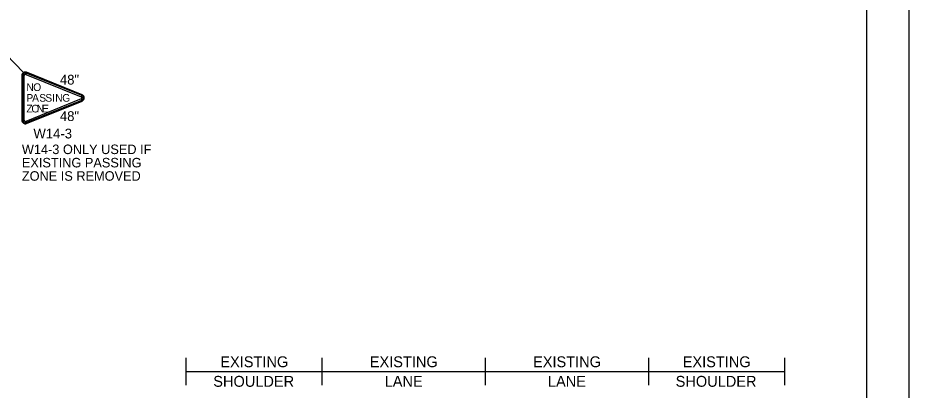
# Model space of a CAD drawing. Extents: x 99976 to 100136, y 99905 to 100011.
# Drawn here: x 100029.51 to 100036.06, y 99943.29 to 99946.03 of the extents above; entities that cross this region are included whole.
import ezdxf

# ---------------------------------------------------------------- set-up
doc = ezdxf.new("R2010")
doc.units = 0
for name, color, linetype in [('Default', 7, 'Continuous'), ('SH_GI_PlotLimits', 7, 'Continuous'), ('SH_GI_SheetBorder', 7, 'Continuous'), ('TR_SN_ConstructionSigns', 7, 'Continuous'), ('TR_WZ_WorkZoneDetails', 7, 'Continuous'), ('TR_WZ_WorkZoneTextCurrent', 7, 'Continuous')]:
    doc.layers.add(name, color=color, linetype=linetype)

msp = doc.modelspace()

# ---------------------------------------------------------------- linework, layer by layer
at = {"layer": 'Default'}
for p, q in [((100029.548, 99945.6015), (100029.5579, 99945.6015)), ((100029.5579, 99945.6015), (100029.548, 99945.6015)), ((100029.548, 99945.6015), (100029.548, 99945.6015)), ((100029.548, 99945.6015), (100029.5579, 99945.6015)), ((100029.5695, 99945.6094), (100029.5732, 99945.6185)), ((100029.5732, 99945.6185), (100029.5695, 99945.6094)), ((100029.5695, 99945.6094), (100029.5732, 99945.6185))]:
    msp.add_line(p, q, dxfattribs=at)
for radius in [0.0183, 0.0183, 0.00844, 0.00844]:
    msp.add_arc((100029.5663, 99945.6015), radius, 67.97569, 180.00001, dxfattribs=at)
at = {"layer": 'SH_GI_PlotLimits'}
msp.add_lwpolyline([(100019.0625, 99939.6875), (100036.0625, 99939.6875), (100036.0625, 99950.6875), (100019.0625, 99950.6875)], close=True, dxfattribs=at)
at = {"layer": 'SH_GI_SheetBorder'}
msp.add_line((100035.75, 99950.375), (100035.75, 99940), dxfattribs=at)
at = {"layer": 'TR_SN_ConstructionSigns'}
for p, q in [((100029.541, 99945.6015), (100029.541, 99945.2716)), ((100029.548, 99945.6015), (100029.548, 99945.2716)), ((100029.548, 99945.6015), (100029.548, 99945.2716)), ((100029.5579, 99945.6015), (100029.548, 99945.6015)), ((100029.5579, 99945.2716), (100029.5579, 99945.6015)), ((100029.5579, 99945.2716), (100029.5579, 99945.6015)), ((100029.5732, 99945.6185), (100029.5695, 99945.6094)), ((100029.5695, 99945.6094), (100029.9773, 99945.4444)), ((100029.5695, 99945.6094), (100029.9773, 99945.4444)), ((100029.981, 99945.4535), (100029.5732, 99945.6185)), ((100029.981, 99945.4535), (100029.5732, 99945.6185)), ((100029.9836, 99945.46), (100029.5758, 99945.625)), ((100029.9773, 99945.4288), (100029.5695, 99945.2638)), ((100029.9773, 99945.4288), (100029.5695, 99945.2638)), ((100029.5732, 99945.2547), (100029.981, 99945.4196)), ((100029.5732, 99945.2547), (100029.981, 99945.4196)), ((100029.5758, 99945.2482), (100029.9836, 99945.4131)), ((100029.981, 99945.4535), (100029.9773, 99945.4444)), ((100029.9773, 99945.4444), (100029.981, 99945.4535)), ((100029.981, 99945.4535), (100029.9773, 99945.4444)), ((100029.9773, 99945.4444), (100029.981, 99945.4535)), ((100029.9773, 99945.4288), (100029.981, 99945.4196)), ((100029.981, 99945.4196), (100029.9773, 99945.4288)), ((100029.9773, 99945.4288), (100029.981, 99945.4196)), ((100029.981, 99945.4196), (100029.9773, 99945.4288)), ((100029.981, 99945.4535), (100029.981, 99945.4535)), ((100029.5579, 99945.2716), (100029.548, 99945.2716)), ((100029.548, 99945.2716), (100029.5579, 99945.2716)), ((100029.5579, 99945.2716), (100029.548, 99945.2716)), ((100029.548, 99945.2716), (100029.5579, 99945.2716)), ((100029.5732, 99945.2547), (100029.5695, 99945.2638)), ((100029.5695, 99945.2638), (100029.5732, 99945.2547)), ((100029.5732, 99945.2547), (100029.5695, 99945.2638)), ((100029.5695, 99945.2638), (100029.5732, 99945.2547)), ((100029.5732, 99945.2547), (100029.5732, 99945.2547))]:
    msp.add_line(p, q, dxfattribs=at)
for centre, radius, start, end in [((100029.5663, 99945.6015), 0.0253, 67.97569, 180), ((100029.9741, 99945.4366), 0.00844, 292.02433, 67.97569), ((100029.9741, 99945.4366), 0.00844, 292.02433, 67.97569), ((100029.9741, 99945.4366), 0.0183, 292.02433, 67.97569), ((100029.9741, 99945.4366), 0.0183, 292.02433, 67.97569), ((100029.9741, 99945.4366), 0.0253, 292.02432, 67.9757), ((100029.5663, 99945.2716), 0.0253, 180, 292.02432), ((100029.5663, 99945.2716), 0.0183, 180.00001, 292.02433), ((100029.5663, 99945.2716), 0.0183, 180.00001, 292.02433), ((100029.5663, 99945.2716), 0.00844, 180.00001, 292.02433), ((100029.5663, 99945.2716), 0.00844, 180.00001, 292.02433)]:
    msp.add_arc(centre, radius, start, end, dxfattribs=at)
at = {"layer": 'TR_WZ_WorkZoneDetails'}
for p, q in [((100029.5522, 99945.6225), (100029.3425, 99945.8393)), ((100030.7479, 99943.3244), (100030.7479, 99943.5244)), ((100031.7479, 99943.3244), (100031.7479, 99943.5244)), ((100032.9479, 99943.3244), (100032.9479, 99943.5244)), ((100034.1479, 99943.3244), (100034.1479, 99943.5244)), ((100035.1479, 99943.3244), (100035.1479, 99943.5244)), ((100030.7479, 99943.4244), (100031.7479, 99943.4244)), ((100031.7479, 99943.4244), (100032.9479, 99943.4244)), ((100032.9479, 99943.4244), (100034.1479, 99943.4244)), ((100034.1479, 99943.4244), (100035.1479, 99943.4244))]:
    msp.add_line(p, q, dxfattribs=at)

# ---------------------------------------------------------------- texts
at = {"layer": 'TR_SN_ConstructionSigns'}
for s, height, p in [('48"', 0.072, (100029.8204, 99945.5347)), ('N', 0.0562, (100029.5744, 99945.4872)), ('O', 0.0562, (100029.6244, 99945.4872)), ('P', 0.0562, (100029.5744, 99945.4085)), ('A', 0.0562, (100029.6163, 99945.4085)), ('S', 0.0562, (100029.6691, 99945.4085)), ('S', 0.0562, (100029.7135, 99945.4085)), ('I', 0.0562, (100029.7622, 99945.4085)), ('N', 0.0562, (100029.786, 99945.4085)), ('G', 0.0562, (100029.8378, 99945.4085)), ('Z', 0.0562, (100029.5744, 99945.3297)), ('O', 0.0562, (100029.6108, 99945.3297)), ('N', 0.0562, (100029.6505, 99945.3297)), ('E', 0.0562, (100029.6891, 99945.3297))]:
    msp.add_text(s, height=height, dxfattribs=at).set_placement(p)
for s, p in [('48"', (100029.8204, 99945.2665)), ('W14-3', (100029.6261, 99945.1383))]:
    msp.add_text(s, height=0.072, rotation=360, dxfattribs=at).set_placement(p)
at = {"layer": 'TR_WZ_WorkZoneDetails'}
for s, p in [('EXISTING', (100030.9996, 99943.4564)), ('EXISTING', (100032.0981, 99943.4564)), ('EXISTING', (100033.2981, 99943.4564)), ('EXISTING', (100034.3981, 99943.4564)), ('SHOULDER', (100030.9476, 99943.3124)), ('LANE', (100032.2075, 99943.3124)), ('LANE', (100033.4075, 99943.3124)), ('SHOULDER', (100034.3461, 99943.3124))]:
    msp.add_text(s, height=0.08, rotation=360, dxfattribs=at).set_placement(p)
at = {"layer": 'TR_WZ_WorkZoneTextCurrent'}
for s, p in [('W14-3 ONLY USED IF ', (100029.541, 99945.0234)), ('EXISTING PASSING', (100029.541, 99944.9254)), ('ZONE IS REMOVED', (100029.541, 99944.8274))]:
    msp.add_text(s, height=0.07, rotation=360, dxfattribs=at).set_placement(p)

doc.saveas('drawing.dxf')
